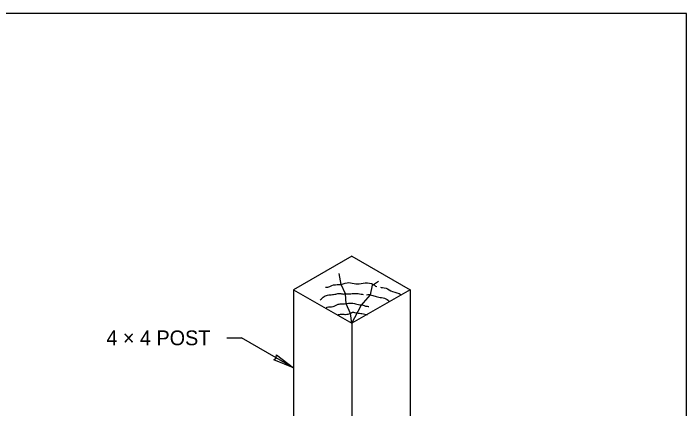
# Model space of a CAD drawing. Extents: x 99862 to 103151, y 100000 to 105076.
# Drawn here: x 102423 to 103151, y 104648 to 105076 of the extents above; entities that cross this region are included whole.
import ezdxf

# ---------------------------------------------------------------- set-up
doc = ezdxf.new("R2010")
doc.units = 0
for name, color, linetype in [('Level 1', 7, 'Continuous'), ('Level 15', 7, 'Continuous'), ('Level 20', 7, 'Continuous'), ('Level 31', 7, 'Continuous'), ('Level 60', 7, 'Continuous')]:
    doc.layers.add(name, color=color, linetype=linetype)

msp = doc.modelspace()

# ---------------------------------------------------------------- linework, layer by layer
at = {"layer": 'Level 1'}
msp.add_lwpolyline([(99862, 102999.5), (103151, 102999.5), (103151, 105075.5), (99862, 105075.5)], close=True, dxfattribs=at)
at = {"layer": 'Level 15'}
for p in [(102653.81, 104724.75), (102726.1, 104692.25)]:
    msp.add_line(p, (102669.81, 104724.75), dxfattribs=at)
msp.add_lwpolyline([(102726.1, 104692.25), (102704.83, 104701.08), (102707.24, 104703.14), (102707.82, 104706.25)], close=True, dxfattribs=at)
at = {"layer": 'Level 31'}
for p, q in [((102789.1, 104813.22), (102726.1, 104776.85)), ((102789.1, 104813.22), (102852.1, 104776.85)), ((102726.1, 104776.85), (102789.1, 104740.47)), ((102852.1, 104776.85), (102789.1, 104740.47)), ((102852.1, 104776.85), (102852.1, 104117.45)), ((102789.1, 104740.47), (102789.1, 104081.07))]:
    msp.add_line(p, q, dxfattribs=at)
for points in [[(102789.1, 104740.47), (102787.67, 104751.23), (102782.81, 104761.71), (102782.21, 104772.24), (102777.76, 104782.34), (102775.52, 104794.3)], [(102789.1, 104740.47), (102799.03, 104759.68), (102809.21, 104771.4), (102811.58, 104781.65), (102818.01, 104785.9)], [(102726.1, 104776.85), (102726.1, 104375.2)]]:
    msp.add_lwpolyline(points, dxfattribs=at)
for points in [[(102760.7, 104779.54), (102764.27, 104779.29), (102769.21, 104783.12), (102777.6, 104781.57), (102786.14, 104785.95), (102793.2, 104782), (102800.93, 104784.38), (102811.17, 104784.24), (102814.4, 104780.8), (102816.21, 104780.18)], [(102754.92, 104765.82), (102756.47, 104766.93), (102759.11, 104769.96), (102763.98, 104771.39), (102769.61, 104771.46), (102774.21, 104772.83), (102777.39, 104773.05), (102778.54, 104771.95), (102783.9, 104772.38), (102789.1, 104772.48), (102795.79, 104772.92), (102800.3, 104771.86), (102801.51, 104771.6)], [(102820.16, 104779.43), (102820.65, 104779.39), (102826.77, 104779.16), (102832.06, 104774.29), (102839.96, 104773.47), (102842.3, 104771.19)], [(102805.06, 104771.28), (102805.59, 104771.35), (102807.9, 104771.96), (102813.05, 104770.3), (102817.99, 104768.57), (102824.44, 104767.98), (102828.57, 104765.64), (102829.61, 104763.86)], [(102761.24, 104756.56), (102762.25, 104758.96), (102767.85, 104757.14), (102772.56, 104761.05), (102776.63, 104761.53), (102777.52, 104761.59)], [(102777.52, 104761.59), (102779.26, 104761.72), (102782.34, 104761.5), (102788.76, 104762.8), (102795.08, 104761.01), (102797.63, 104760.49), (102800.74, 104760.7), (102803.79, 104758.74), (102806.43, 104758.95), (102807.4, 104758.53)], [(102773.27, 104749.61), (102773.9, 104749.77), (102776.84, 104750.59), (102780.74, 104750.37), (102782.21, 104749.97), (102785.09, 104750.45), (102788.72, 104751.49), (102789.1, 104752.94), (102794.91, 104751.43), (102799.71, 104751.21), (102804.42, 104749.9), (102805.65, 104749.54)]]:
    msp.add_open_spline(points, degree=3, dxfattribs=at)
at = {"layer": 'Level 60'}
msp.add_line((103151, 105075.5), (103151, 105075.5), dxfattribs=at)

# ---------------------------------------------------------------- texts
at = {"layer": 'Level 20'}
msp.add_text('4 × 4 POST', height=16, dxfattribs=at).set_placement((102523.75, 104716.76))

doc.saveas('drawing.dxf')
